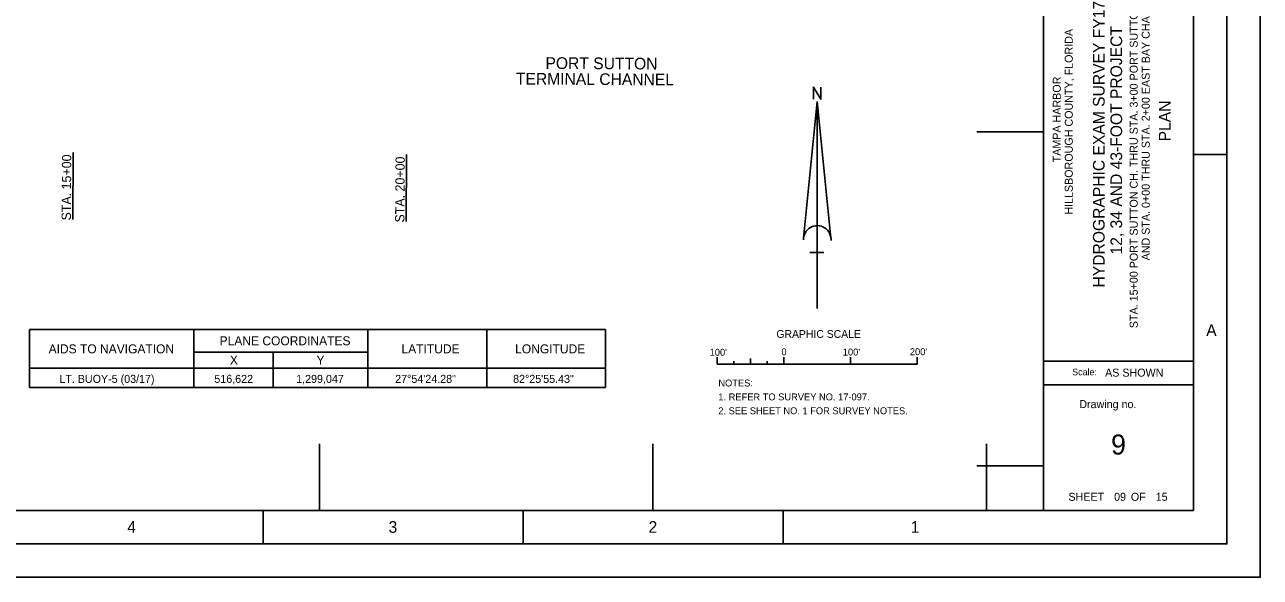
# Model space of a CAD drawing. Extents: x 515010 to 519411, y 1296833 to 1300233.
# Drawn here: x 517558 to 519411, y 1296833 to 1297660 of the extents above; entities that cross this region are included whole.
import ezdxf

# ---------------------------------------------------------------- set-up
doc = ezdxf.new("R2010")
doc.units = 0
for name, color, linetype in [('G-ANNO-NPLT', 7, 'Continuous'), ('G-ANNO-TEXT-DRWG', 7, 'Continuous'), ('G-ANNO-TEXT-PROJ', 7, 'Continuous'), ('G-ANNO-TEXT-TTLB', 7, 'Continuous'), ('G-ANNO-TTLB', 7, 'Continuous'), ('V-ALGN-TEXT', 7, 'Continuous'), ('V-ANNO-NOTE', 7, 'Continuous'), ('V-ANNO-SCHD', 7, 'Continuous'), ('V-ANNO-SYMB', 7, 'Continuous'), ('V-CHAN-CNTR-IDEN', 7, 'Continuous'), ('V-TOPO-COOR-STAT', 7, 'Continuous')]:
    doc.layers.add(name, color=color, linetype=linetype)

msp = doc.modelspace()

# ---------------------------------------------------------------- linework, layer by layer
at = {"layer": 'G-ANNO-NPLT'}
msp.add_lwpolyline([(515010.4, 1300233), (519410.4, 1300233), (519410.4, 1296833), (515010.4, 1296833)], close=True, dxfattribs=at)
msp.add_lwpolyline([(519410.6, 1296883), (519410.6, 1296833), (519360.6, 1296833)], dxfattribs=at)
at = {"layer": 'G-ANNO-TTLB'}
for p, q in [((519085.4, 1300133), (519085.4, 1296933)), ((519360.4, 1297466.3), (519310.4, 1297466.3)), ((519085.4, 1297156.7), (519310.4, 1297156.7)), ((519085.4, 1297121.1), (519310.4, 1297121.1)), ((517915.4, 1296883), (517915.4, 1296933)), ((518305.4, 1296883), (518305.4, 1296933)), ((518695.4, 1296883), (518695.4, 1296933))]:
    msp.add_line(p, q, dxfattribs=at)
for points in [[(515060.4, 1296883), (519360.4, 1296883), (519360.4, 1300183), (515060.4, 1300183)], [(519310.4, 1300133), (515185.4, 1300133), (515185.4, 1296933), (519310.4, 1296933)]]:
    msp.add_lwpolyline(points, close=True, dxfattribs=at)
at = {"layer": 'V-ALGN-TEXT'}
for p, q in [((517630.1, 1297368.9), (517630.7, 1297468.9)), ((518130.1, 1297365.9), (518130.7, 1297465.9))]:
    msp.add_line(p, q, dxfattribs=at)
at = {"layer": 'V-ANNO-NOTE'}
for p, q in [((518596.3, 1297152), (518596.3, 1297162.4)), ((518596.3, 1297152), (518896.3, 1297152)), ((518621.3, 1297152), (518621.3, 1297156.8)), ((518646.3, 1297152), (518646.3, 1297160.5)), ((518671.3, 1297152), (518671.3, 1297156.8)), ((518696.3, 1297152), (518696.3, 1297162.4)), ((518696.3, 1297152), (518696.3, 1297162.4)), ((518696.3, 1297152), (518696.3, 1297157)), ((518796.3, 1297152), (518796.3, 1297162.4)), ((518896.3, 1297152), (518896.3, 1297162.4))]:
    msp.add_line(p, q, dxfattribs=at)
at = {"layer": 'V-ANNO-SCHD'}
for p, q in [((517565, 1297203.9), (518429, 1297203.9)), ((517565, 1297203.9), (517565, 1297117.3)), ((517811.6, 1297203.9), (517811.6, 1297117.3)), ((518072.3, 1297203.9), (518072.3, 1297117.3)), ((518250.7, 1297203.9), (518250.7, 1297117.3)), ((518429, 1297117.3), (518429, 1297203.9)), ((517811.6, 1297170.3), (518072.3, 1297170.3)), ((517930.5, 1297170.3), (517930.5, 1297117.3)), ((517565, 1297146.2), (518429, 1297146.2)), ((517565, 1297117.3), (518429, 1297117.3))]:
    msp.add_line(p, q, dxfattribs=at)
at = {"layer": 'V-ANNO-SYMB'}
for p, q in [((518725.7, 1297340.9), (518746.3, 1297545.7)), ((518746.3, 1297235.4), (518746.3, 1297545.7)), ((518766.9, 1297340.9), (518746.3, 1297545.7)), ((518756.1, 1297319.2), (518735.4, 1297319.2))]:
    msp.add_line(p, q, dxfattribs=at)
msp.add_lwpolyline([(518740.5, 1297549), (518740.5, 1297567.1), (518751.8, 1297549), (518751.8, 1297567.1)], dxfattribs=at)
msp.add_arc((518746.3, 1297338.9), 20.7, 355.2984, 182.0673, dxfattribs=at)
at = {"layer": 'V-TOPO-COOR-STAT'}
for p, q in [((519085.4, 1297500), (518985.4, 1297500)), ((518000, 1296933), (518000, 1297033)), ((518500, 1296933), (518500, 1297033)), ((519000, 1296933), (519000, 1297033)), ((519085.4, 1297000), (518985.4, 1297000))]:
    msp.add_line(p, q, dxfattribs=at)

# ---------------------------------------------------------------- texts
at = {"layer": 'G-ANNO-TEXT-DRWG'}
for s, height, p in [('STA. 15+00 PORT SUTTON CH. THRU STA. 3+00 PORT SUTTON TERMINAL CH.', 12, (519226.8, 1297206.1)), ('AND STA. 0+00 THRU STA. 2+00 EAST BAY CHANNEL', 12, (519244.8, 1297307.6)), ('PLAN', 17.5, (519276, 1297485.8))]:
    msp.add_text(s, height=height, rotation=90, dxfattribs=at).set_placement(p)
for s, height, p in [('9', 30, (519186.8, 1297016.8)), (' 09          15', 12, (519186.9, 1296947.5))]:
    msp.add_text(s, height=height, dxfattribs=at).set_placement(p)
at = {"layer": 'G-ANNO-TEXT-PROJ'}
for s, height, p in [('HYDROGRAPHIC EXAM SURVEY FY17', 17.5, (519177.2, 1297267)), ('HILLSBOROUGH COUNTY, FLORIDA', 12, (519129.4, 1297376)), ('12, 34 AND 43-FOOT PROJECT', 17.5, (519203.4, 1297316.4)), ('TAMPA HARBOR', 12, (519111.4, 1297454.4))]:
    msp.add_text(s, height=height, rotation=90, dxfattribs=at).set_placement(p)
at = {"layer": 'G-ANNO-TEXT-TTLB'}
for s, height, p in [('Scale:', 10, (519128.5, 1297135.4)), ('AS SHOWN', 12, (519177.9, 1297133.4)), ('Drawing no.', 12, (519139.2, 1297086.3)), ('SHEET         OF', 12, (519122.9, 1296947.5))]:
    msp.add_text(s, height=height, dxfattribs=at).set_placement(p)
at = {"layer": 'G-ANNO-TTLB'}
for s, p in [('A', (519329.5, 1297194.2)), ('4', (517711.8, 1296899.6)), ('3', (518103.6, 1296899.6)), ('2', (518493.4, 1296899.6)), ('1', (518886.5, 1296899.6))]:
    msp.add_text(s, height=17.5, dxfattribs=at).set_placement(p)
at = {"layer": 'V-ALGN-TEXT'}
for s, p in [('STA. 15+00', (517627.3, 1297367.3)), ('STA. 20+00', (518127.3, 1297364.2))]:
    msp.add_text(s, height=13.92, rotation=89.6504, dxfattribs=at).set_placement(p)
at = {"layer": 'V-ANNO-NOTE'}
for s, height, p in [('GRAPHIC SCALE', 11.666, (518685.1, 1297191.5)), ("100'", 10.42, (518585, 1297164.7)), ('0', 10.4, (518692.6, 1297165.4)), ("100'", 10.42, (518784.6, 1297165.1)), ("200'", 10.42, (518885.2, 1297165.6)), ('NOTES:', 10.42, (518598, 1297118.7)), ('1. REFER TO SURVEY NO. 17-097.', 10.416, (518598, 1297097.9)), ('2. SEE SHEET NO. 1 FOR SURVEY NOTES.', 10.416, (518598, 1297077.1))]:
    msp.add_text(s, height=height, dxfattribs=at).set_placement(p)
at = {"layer": 'V-ANNO-SCHD'}
for s, height, p in [('PLANE COORDINATES', 13.471, (517850.3, 1297180.4)), ('AIDS TO NAVIGATION', 13.471, (517593.9, 1297168.3)), ('LATITUDE', 13.47, (518123, 1297168.3)), ('LONGITUDE', 13.47, (518293.4, 1297168.3)), ('X', 13.5, (517865.7, 1297151.5)), ('Y', 13.5, (517995.5, 1297151.5))]:
    msp.add_text(s, height=height, rotation=0.0001, dxfattribs=at).set_placement(p)
at = {"layer": 'V-ANNO-SYMB'}
for s, p in [('LT. BUOY-5 (03/17)', (517610, 1297124.1)), ('516,622', (517842.4, 1297124.1)), ('1,299,047', (517965.1, 1297124.1)), ('27%%D54\'24.28"', (518113.5, 1297124.1)), ('82%%D25\'55.43"', (518290.3, 1297124.1))]:
    msp.add_text(s, height=12, dxfattribs=at).set_placement(p)
at = {"layer": 'V-CHAN-CNTR-IDEN'}
for s, p in [('PORT SUTTON', (518338.8, 1297594.4)), ('TERMINAL CHANNEL', (518294.5, 1297571))]:
    msp.add_text(s, height=17.52, rotation=359.6501, dxfattribs=at).set_placement(p)

doc.saveas('drawing.dxf')
